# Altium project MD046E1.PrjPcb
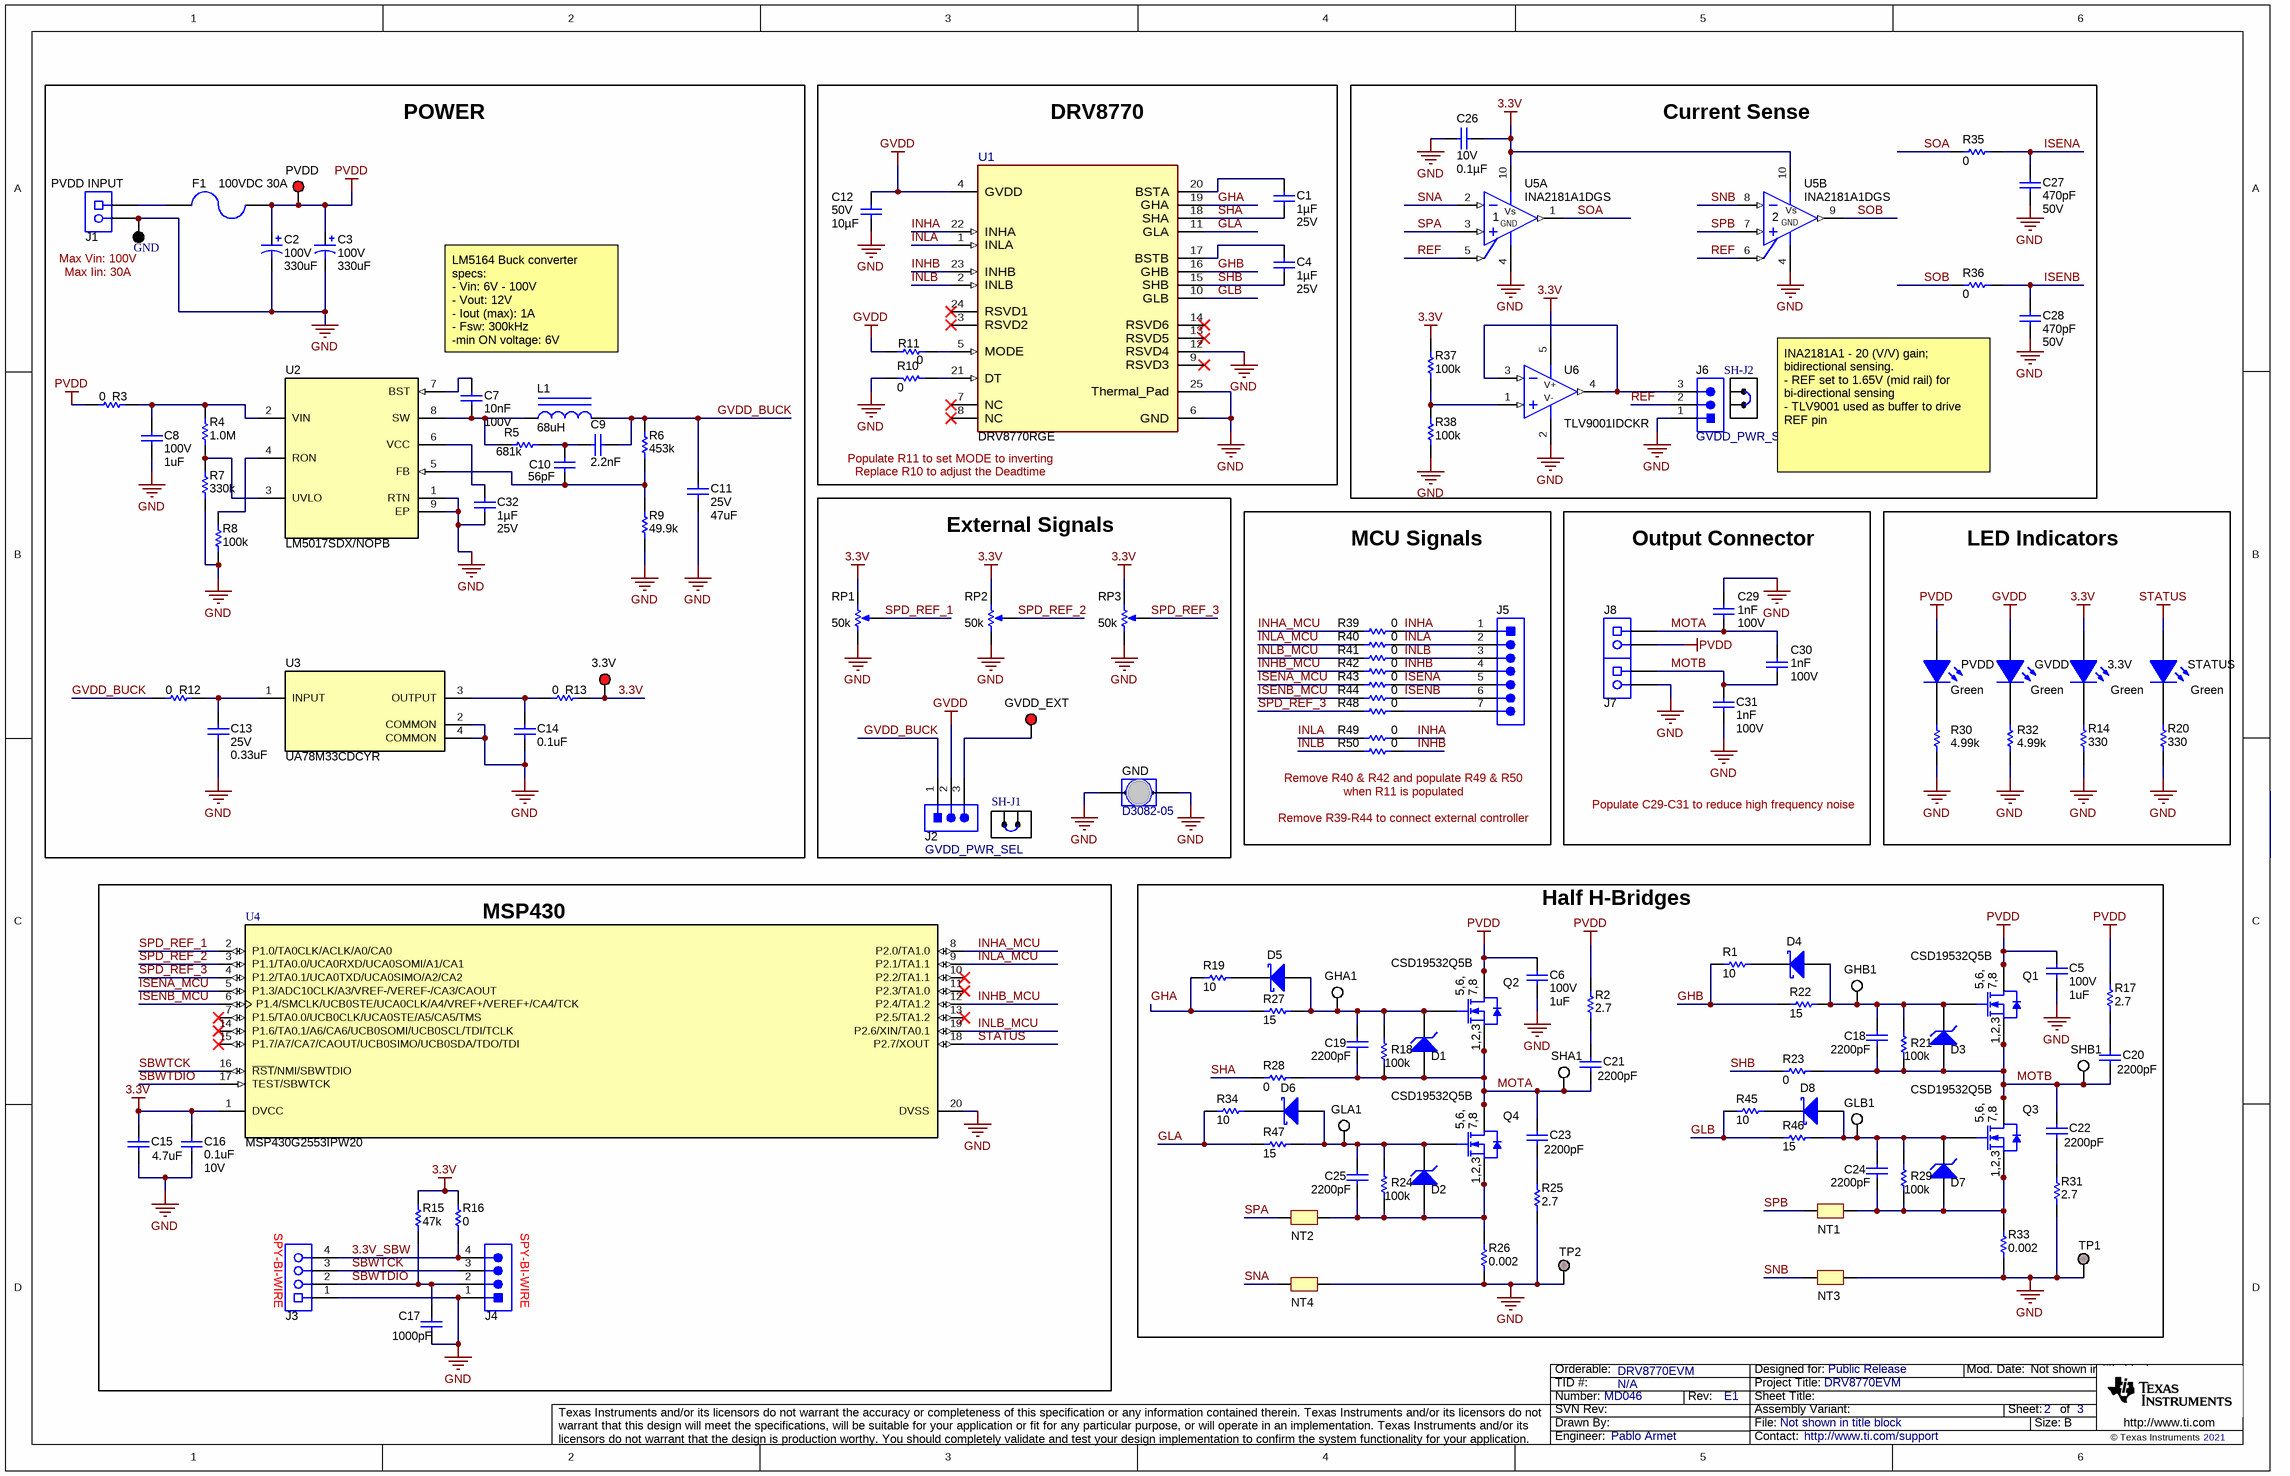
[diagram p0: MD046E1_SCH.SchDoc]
CopyrightYear: 2021; EVM_orderable: DRV8770EVM; PCB_Layout: Pablo Armet; PCB_Rev: E1; PRJ_Customer: Public Release; PRJ_Engineer: Pablo Armet; PRJ_Number: MD046; PRJ_Title: DRV8770EVM; SCH_Rev: E1; TechSupport: http://www.ti.com/support; TID: N/A
1 sheet, 136 parts. Net scope: global (net labels, ports and power ports of the same name join across sheets).
Board file: MD046E1_PCB.PcbDoc

## Sheet MD046E1_SCH.SchDoc
size 431 x 279 mm; Date: Not shown in title block; ApprovedBy: Not shown in title block; CheckedBy: Not shown in title block; Author: Not shown in title block; CompanyName: Not shown in title block; Engineer: Not shown in title block; Organization: Not shown in title block; Address1: Not shown in title block; Address2: Not shown in title block; Address3: Not shown in title block; Address4: Not shown in title block; DocumentNumber: 2; Revision: Use project parameter SCH_Rev; SheetNumber: 2; SheetTotal: 3; PageSetup: Record=PageOptions¦CenterHorizontal=True¦CenterVertical=True¦PrintScale=1.00¦XCorrection=1.00¦YCorrection=1.00¦PrintKind=0¦BorderSize=5000000¦LeftOffset=0¦BottomOffset=0¦Orientation=2¦PaperLength=1000¦PaperWidth=1000¦Scale=100¦PaperSource=15¦PrintQuality=600¦MediaType=1¦DitherType=10¦PaperKind=Letter¦PrintScaleMode=1

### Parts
(Parts that share a designator on the sheet are numbered #1, #2 ... from top to bottom, then left to right.)
3.3V#1  value Green  [LED_LTST-C171]
3.3V#2  (no value)  [Keystone5000]
C1  Cap_F: 1µF  VDC_V: 25V  [0805L]  (hidden comment: CL21B105KAFNNNE)
C2  VDC_V: 100V  ValueDisplayed: 330uF  [SM_RADIAL_K16]  (hidden comment: EEV-FK2A331M)
C3  VDC_V: 100V  ValueDisplayed: 330uF  [SM_RADIAL_K16]  (hidden comment: EEV-FK2A331M)
C4  Cap_F: 1µF  VDC_V: 25V  [0805L]  (hidden comment: CL21B105KAFNNNE)
C5  VDC_V: 100V  ValueDisplayed: 1uF  [1210_220L]  (hidden comment: CGA6M2X7R2A105K200AA)
C6  VDC_V: 100V  ValueDisplayed: 1uF  [1210_220L]  (hidden comment: CGA6M2X7R2A105K200AA)
C7  Cap_F: 10nF  VDC_V: 100V  [0603L]  (hidden comment: C0603C103J1RACTU)
C8  VDC_V: 100V  ValueDisplayed: 1uF  [1210_220]  (hidden comment: CGA6M2X7R2A105K200AA)
C9  Cap_F: 2.2nF  [0603L]  (hidden comment: CGA3E2X7R2A222K080AA)
C10  ValueDisplayed: 56pF  [0603L]  (hidden comment: GRM1885C2A560JA01D)
C11  VDC_V: 25V  ValueDisplayed: 47uF  [1206_190L]  (hidden comment: C3216X5R1E476M160AC)
C12  VDC_V: 50V  ValueDisplayed: 10µF  [1210_270L]  (hidden comment: CL32B106KBJNNWE)
C13  VDC_V: 25V  ValueDisplayed: 0.33uF  [0805L]  (hidden comment: 08053D334KAT2A)
C14  ValueDisplayed: 0.1uF  [0603L]  (hidden comment: C0603C104J4RACTU)
C15  ValueDisplayed: 4.7uF  [0402_065L]  (hidden comment: C1005X5R1A475K050BC)
C16  ValueDisplayed: 0.1uF  VDC_V: 10V  [0603L]  (hidden comment: C0603C104K8RACTU)
C17  ValueDisplayed: 1000pF  [0603L]  (hidden comment: C0603C102J5RACAUTO)
C18  ValueDisplayed: 2200pF  [0603L]  (hidden comment: 06031C222KAT2A)
C19  ValueDisplayed: 2200pF  [0603L]  (hidden comment: 06031C222KAT2A)
C20  ValueDisplayed: 2200pF  [0603L]  (hidden comment: GRM188R72A222KA01D)
C21  ValueDisplayed: 2200pF  [0603L]  (hidden comment: GRM188R72A222KA01D)
C22  ValueDisplayed: 2200pF  [0603L]  (hidden comment: GRM188R72A222KA01D)
C23  ValueDisplayed: 2200pF  [0603L]  (hidden comment: GRM188R72A222KA01D)
C24  ValueDisplayed: 2200pF  [0603L]  (hidden comment: 06031C222KAT2A)
C25  ValueDisplayed: 2200pF  [0603L]  (hidden comment: 06031C222KAT2A)
C26  VDC_V: 10V  ValueDisplayed: 0.1µF  [0402L]  (hidden comment: C0402C104K8RACAUTO)
C27  Cap_F: 470pF  VDC_V: 50V  [0603L]  (hidden comment: 885012206081)
C28  Cap_F: 470pF  VDC_V: 50V  [0603L]  (hidden comment: 885012206081)
C29  Cap_F: 1nF  VDC_V: 100V  [0603L]  (hidden comment: 06031C102JAT2A)
C30  Cap_F: 1nF  VDC_V: 100V  [0603L]  (hidden comment: 06031C102JAT2A)
C31  Cap_F: 1nF  VDC_V: 100V  [0603L]  (hidden comment: 06031C102JAT2A)
C32  Cap_F: 1µF  VDC_V: 25V  [0805L]  (hidden comment: CL21B105KAFNNNE)
D1  SMAZ16-13-F  [SMA]  (value not drawn)
D2  SMAZ16-13-F  [SMA]  (value not drawn)
D3  SMAZ16-13-F  [SMA]  (value not drawn)
D4  SSA24-E3/61T  [SMA]  (value not drawn)
D5  SSA24-E3/61T  [SMA]  (value not drawn)
D6  SSA24-E3/61T  [SMA]  (value not drawn)
D7  SMAZ16-13-F  [SMA]  (value not drawn)
D8  SSA24-E3/61T  [SMA]  (value not drawn)
F1  100VDC 30A  [Fuse_0463]
GHA1  5002  [Keystone5002]  (value not drawn)
GHB1  5002  [Keystone5002]  (value not drawn)
GLA1  5002  [Keystone5002]  (value not drawn)
GLB1  5002  [Keystone5002]  (value not drawn)
GND#1  5001  [Keystone5001]  (value not drawn)
GND#2  D3082-05  [Harwin_D3082-05]
GVDD  value Green  [LED_LTST-C171]
GVDD_EXT  (no value)  [Keystone5000]
J1  PVDD INPUT  [Phoenix_1902547]
J2  GVDD_PWR_SEL  [WURTH_61300311121]
J3  851-43-004-20-001000  [CONN_851-43-004-20-001000]  (value not drawn)
J4  TSW-104-07-G-S  [TSW-104-07-G-S]  (value not drawn)
J5  PBC07SFAN  [Sullins_xxC07SFAN]  (value not drawn)
J6  GVDD_PWR_SEL  [WURTH_61300311121]
J7  (no value)  [Phoenix_1902547]
J8  (no value)  [Phoenix_1902547]
L1  ValueDisplayed: 68uH  [SDR1006]  (hidden comment: SDR1006-680KL)
NT1  Net-Tie  [Net-Tie_10mil]  (value not drawn)  (net tie, no BOM)
NT2  Net-Tie  [Net-Tie_10mil]  (value not drawn)  (net tie, no BOM)
NT3  Net-Tie  [Net-Tie_10mil]  (value not drawn)  (net tie, no BOM)
NT4  Net-Tie  [Net-Tie_10mil]  (value not drawn)  (net tie, no BOM)
PVDD#1  5000  [Keystone5000]  (value not drawn)
PVDD#2  value Green  [LED_LTST-C171]
Q1  CSD19532Q5B  [DNK0008A]
Q2  CSD19532Q5B  [DNK0008A]
Q3  CSD19532Q5B  [DNK0008A]
Q4  CSD19532Q5B  [DNK0008A]
R1  ValueDisplayed: 10  [0805L]  (hidden comment: ERJ-6GEYJ100V)
R2  ValueDisplayed: 2.7  [0805L]  (hidden comment: CRCW08052R70JNEA)
R3  value 0  [0603L]  (hidden comment: CRCW06030000Z0EA)
R4  ValueDisplayed: 1.0M  [0603L]  (hidden comment: CRCW06031M00JNEA)
R5  ValueDisplayed: 681k  [0603L]  (hidden comment: RC0603FR-07681KL)
R6  ValueDisplayed: 453k  [0603L]  (hidden comment: RC0603FR-07453KL)
R7  ValueDisplayed: 330k  [0603L]  (hidden comment: CRCW0603330KJNEA)
R8  ValueDisplayed: 100k  [0402L]  (hidden comment: CRCW0402100KFKED)
R9  ValueDisplayed: 49.9k  [0603L]  (hidden comment: RC0603FR-0749K9L)
R10  ValueDisplayed: 0  [0805L]  (hidden comment: CRCW08050000Z0EAHP)
R11  value 0  [0603L]  (hidden comment: CRCW06030000Z0EA)
R12  value 0  [0603L]  (hidden comment: CRCW06030000Z0EA)
R13  value 0  [0603L]  (hidden comment: CRCW06030000Z0EA)
R14  ValueDisplayed: 330  [0603L]  (hidden comment: CRCW0603330RJNEA)
R15  ValueDisplayed: 47k  [0603L]  (hidden comment: CRCW060347K0JNEA)
R16  ValueDisplayed: 0  [0603L]  (hidden comment: CRCW06030000Z0EA)
R17  ValueDisplayed: 2.7  [0805L]  (hidden comment: CRCW08052R70JNEA)
R18  ValueDisplayed: 100k  [0603L]  (hidden comment: CRCW0603100KFKEA)
R19  ValueDisplayed: 10  [0805L]  (hidden comment: ERJ-6GEYJ100V)
R20  ValueDisplayed: 330  [0603L]  (hidden comment: CRCW0603330RJNEA)
R21  ValueDisplayed: 100k  [0603L]  (hidden comment: CRCW0603100KFKEA)
R22  ValueDisplayed: 15  [0805L]  (hidden comment: ERJ-6GEYJ150V)
R23  ValueDisplayed: 0  [0603L]  (hidden comment: RCS06030000Z0EA)
R24  ValueDisplayed: 100k  [0603L]  (hidden comment: CRCW0603100KFKEA)
R25  ValueDisplayed: 2.7  [0805L]  (hidden comment: CRCW08052R70JNEA)
R26  ValueDisplayed: 0.002  [LRMA2512_under3]  (hidden comment: LRMAP2512-R002FT4)
R27  ValueDisplayed: 15  [0805L]  (hidden comment: ERJ-6GEYJ150V)
R28  ValueDisplayed: 0  [0603L]  (hidden comment: RCS06030000Z0EA)
R29  ValueDisplayed: 100k  [0603L]  (hidden comment: CRCW0603100KFKEA)
R30  value 4.99k  [0603L]  (hidden comment: CRCW06034K99FKEA)
R31  ValueDisplayed: 2.7  [0805L]  (hidden comment: CRCW08052R70JNEA)
R32  value 4.99k  [0603L]  (hidden comment: CRCW06034K99FKEA)
R33  ValueDisplayed: 0.002  [LRMA2512_under3]  (hidden comment: LRMAP2512-R002FT4)
R34  ValueDisplayed: 10  [0805L]  (hidden comment: ERJ-6GEYJ100V)
R35  ValueDisplayed: 0  [0603L]  (hidden comment: RCS06030000Z0EA)
R36  ValueDisplayed: 0  [0603L]  (hidden comment: RCS06030000Z0EA)
R37  ValueDisplayed: 100k  [0603L]  (hidden comment: CRCW0603100KFKEA)
R38  ValueDisplayed: 100k  [0603L]  (hidden comment: CRCW0603100KFKEA)
R39  ValueDisplayed: 0  [0603L]  (hidden comment: RCS06030000Z0EA)
R40  ValueDisplayed: 0  [0603L]  (hidden comment: RCS06030000Z0EA)
R41  ValueDisplayed: 0  [0603L]  (hidden comment: RCS06030000Z0EA)
R42  ValueDisplayed: 0  [0603L]  (hidden comment: RCS06030000Z0EA)
R43  ValueDisplayed: 0  [0603L]  (hidden comment: RCS06030000Z0EA)
R44  ValueDisplayed: 0  [0603L]  (hidden comment: RCS06030000Z0EA)
R45  ValueDisplayed: 10  [0805L]  (hidden comment: ERJ-6GEYJ100V)
R46  ValueDisplayed: 15  [0805L]  (hidden comment: ERJ-6GEYJ150V)
R47  ValueDisplayed: 15  [0805L]  (hidden comment: ERJ-6GEYJ150V)
R48  ValueDisplayed: 0  [0603L]  (hidden comment: RCS06030000Z0EA)
R49  ValueDisplayed: 0  [0603L]  (hidden comment: RCS06030000Z0EA)
R50  ValueDisplayed: 0  [0603L]  (hidden comment: RCS06030000Z0EA)
RP1  value 50k  [Bourns_3352T]  (hidden comment: 3352T-1-503LF)
RP2  value 50k  [Bourns_3352T]  (hidden comment: 3352T-1-503LF)
RP3  value 50k  [Bourns_3352T]  (hidden comment: 3352T-1-503LF)
SH-J1  SNT-100-BK-G  [SNT-100-BK-G]  (value not drawn)
SH-J2  SNT-100-BK-G  [SNT-100-BK-G]  (value not drawn)
SHA1  5002  [Keystone5002]  (value not drawn)
SHB1  5002  [Keystone5002]  (value not drawn)
STATUS  value Green  [LED_LTST-C171]
TP1  TP_SM_1MM  [TP_SM_1MM]  (value not drawn)  (no BOM)
TP2  TP_SM_1MM  [TP_SM_1MM]  (value not drawn)  (no BOM)
U1  DRV8770RGE  [RGE0024B-MFG]
U2  LM5017SDX/NOPB  [NGU0008B]
U3  UA78M33CDCYR  [DCY0004A_N]
U4  MSP430G2553IPW20  [PW0020A_N]
U5  INA2181A1DGS  [DGS0010A_N]  (parts A,B of 2)
U6  TLV9001IDCKR  [DCK0005A_N]

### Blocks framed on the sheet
POWER: 3.3V#2 C2 C3 C7-C11 C13 C14 C32 F1 GND#1 J1 L1 PVDD#1 R3-R9 R12 R13 U2 U3
DRV8770: C1 C4 C12 R10 R11 U1
Current Sense: C26-C28 J6 R35-R38 SH-J2 U5 U6
External Signals: GND#2 GVDD_EXT J2 RP1-RP3 SH-J1
MCU Signals: J5 R39-R44 R48-R50
Output Connector: C29-C31 J7 J8
LED Indicators: 3.3V#1 GVDD PVDD#2 R14 R20 R30 R32 STATUS
MSP430: C15-C17 J3 J4 R15 R16 U4
Half H-Bridges: C5 C6 C18-C25 D1-D8 GHA1 GHB1 GLA1 GLB1 NT1-NT4 Q1-Q4 R1 R2 R17-R19 R21-R29 R31 R33 R34 R45-R47 SHA1 SHB1 TP1 TP2

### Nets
3.3V: 3.3V#1.1(A) 3.3V#2.1 C15.1 C16.1 C26.1 R13.2 R15.2 R16.2 R37.2 RP1.3(CW) RP2.3(CW) RP3.3(CW) U4.1(DVCC) U5.10(VS) U6.5(V+)
GND: C2.2(-) C3.2(-) C5.2 C6.2 C8.2 C11.2 C12.2 C13.2 C14.2 C15.2 C16.2 C17.2 C26.2 C27.2 C28.2 C29.1 C31.2 C32.2 GND#1.1 GND#2.1 GND#2.2 J1.2 J3.1 J4.1 J6.1 J7.2 NT3.2 NT4.2 R7.1 R8.1 R9.1 R10.1 R14.1 R20.1 R25.1 R26.1 R30.1 R31.1 R32.1 R33.1 R38.1 RP1.1(CCW) RP2.1(CCW) RP3.1(CCW) TP1.1 TP2.1 U1.6(GND) U1.12(RSVD4) U1.25(Thermal_Pad) U2.1(RTN) U2.9(EP) U3.2(COMMON) U3.4(COMMON) U4.20(DVSS) U5.4(GND) U6.2(V-)
GVDD: C12.1 GVDD.1(A) J2.2 R11.2 U1.4(GVDD)
PVDD: C2.1(+) C3.1(+) C5.1 C6.1 F1.1 J8.2 PVDD#1.1 PVDD#2.1(A) Q1.5(D) Q1.6(D) Q1.7(D) Q1.8(D) Q1.9(D) Q2.5(D) Q2.6(D) Q2.7(D) Q2.8(D) Q2.9(D) R2.2 R3.1 R17.2
STATUS: STATUS.1(A) U4.18(P2.7/XOUT)
3.3V_SBW: J3.4 J4.4 R16.1
GHA: R19.1 R27.1 U1.19(GHA)
GHB: R1.1 R22.1 U1.16(GHB)
GLA: R34.1 R47.1 U1.11(GLA)
GLB: R45.1 R46.1 U1.10(GLB)
GVDD_BUCK: C9.1 C11.1 J2.1 L1.2 R6.2 R12.1
INHA: J5.1 R39.2 R49.2 U1.22(INHA)
INHA_MCU: R39.1 U4.8(P2.0/TA1.0)
INHB: J5.4 R42.2 R50.2 U1.23(INHB)
INHB_MCU: R42.1 U4.12(P2.4/TA1.2)
INLA: J5.2 R40.2 R49.1 U1.1(INLA)
INLA_MCU: R40.1 U4.9(P2.1/TA1.1)
INLB: J5.3 R41.2 R50.1 U1.2(INLB)
INLB_MCU: R41.1 U4.19(P2.6/XIN/TA0.1)
ISENA: C27.1 J5.5 R35.2 R43.2
ISENA_MCU: R43.1 U4.5(P1.3/ADC10CLK/A3/VREF-/VEREF-/CA3/CAOUT)
ISENB: C28.1 J5.6 R36.2 R44.2
ISENB_MCU: R44.1 U4.6(P1.4/SMCLK/UCB0STE/UCA0CLK/A4/VREF+/VEREF+/CA4/TCK)
MOTA: C19.2 C21.2 C23.1 C29.2 C30.1 D1.2(A) J8.1 Q2.1(S) Q2.2(S) Q2.3(S) Q4.5(D) Q4.6(D) Q4.7(D) Q4.8(D) Q4.9(D) R18.2 R28.2 SHA1.1
MOTB: C18.2 C20.2 C22.1 C30.2 C31.1 D3.2(A) J7.1 Q1.1(S) Q1.2(S) Q1.3(S) Q3.5(D) Q3.6(D) Q3.7(D) Q3.8(D) Q3.9(D) R21.2 R23.2 SHB1.1
REF: J6.2 U5.5(REF1) U5.6(REF2)
SBWTCK: J3.3 J4.3 U4.16(~{RST}/NMI/SBWTDIO)
SBWTDIO: C17.1 J3.2 J4.2 R15.1 U4.17(TEST/SBWTCK)
SHA: C1.2 R28.1 U1.18(SHA)
SHB: C4.2 R23.1 U1.15(SHB)
SNA: NT4.1 U5.2(IN-1)
SNB: NT3.1 U5.8(IN-2)
SOA: R35.1 U5.1(OUT1)
SOB: R36.1 U5.9(OUT2)
SPA: NT2.1 U5.3(IN+1)
SPB: NT1.1 U5.7(IN+2)
SPD_REF_1: RP1.2(WIPER) U4.2(P1.0/TA0CLK/ACLK/A0/CA0)
SPD_REF_2: RP2.2(WIPER) U4.3(P1.1/TA0.0/UCA0RXD/UCA0SOMI/A1/CA1)
SPD_REF_3: R48.1 RP3.2(WIPER) U4.4(P1.2/TA0.1/UCA0TXD/UCA0SIMO/A2/CA2)
Net3.3V#1_2: 3.3V#1.2(K) R14.2
NetC1_1: C1.1 U1.20(BSTA)
NetC4_1: C4.1 U1.17(BSTB)
NetC7_1: C7.1 U2.7(BST)
NetC7_2: C7.2 L1.1 R5.1 U2.8(SW)
NetC8_1: C8.1 R3.2 R4.2 U2.2(VIN)
NetC9_2: C9.2 C10.1 R5.2
NetC10_2: C10.2 R6.1 R9.2 U2.5(FB)
NetC13_1: C13.1 R12.2 U3.1(INPUT)
NetC14_1: C14.1 R13.1 U3.3(OUTPUT)
NetC18_1: C18.1 D3.1(K) D4.2(A) GHB1.1 Q1.4(G) R21.1 R22.2
NetC19_1: C19.1 D1.1(K) D5.2(A) GHA1.1 Q2.4(G) R18.1 R27.2
NetC20_1: C20.1 R17.1
NetC21_1: C21.1 R2.1
NetC22_2: C22.2 R31.2
NetC23_2: C23.2 R25.2
NetC24_1: C24.1 D7.1(K) D8.2(A) GLB1.1 Q3.4(G) R29.1 R46.2
NetC24_2: C24.2 D7.2(A) NT1.2 Q3.1(S) Q3.2(S) Q3.3(S) R29.2 R33.2
NetC25_1: C25.1 D2.1(K) D6.2(A) GLA1.1 Q4.4(G) R24.1 R47.2
NetC25_2: C25.2 D2.2(A) NT2.2 Q4.1(S) Q4.2(S) Q4.3(S) R24.2 R26.2
NetC32_1: C32.1 U2.6(VCC)
NetD4_1: D4.1(K) R1.2
NetD5_1: D5.1(K) R19.2
NetD6_1: D6.1(K) R34.2
NetD8_1: D8.1(K) R45.2
NetF1_2: F1.2 J1.1
NetGVDD_2: GVDD.2(K) R32.2
NetGVDD_EXT_1: GVDD_EXT.1 J2.3
NetJ5_7: J5.7 R48.2
NetJ6_3: J6.3 U6.3(IN-) U6.4(OUT)
NetPVDD#2_2: PVDD#2.2(K) R30.2
NetR4_1: R4.1 R7.2 U2.3(UVLO)
NetR8_2: R8.2 U2.4(RON)
NetR10_2: R10.2 U1.21(DT)
NetR11_1: R11.1 U1.5(MODE)
NetR20_2: R20.2 STATUS.2(K)
NetR37_1: R37.1 R38.2 U6.1(IN+)

Not connected (* = marked no-connect by the designer): U1 3(RSVD2)* 7(NC)* 8(NC)* 9(RSVD3)* 13(RSVD5)* 14(RSVD6)* 24(RSVD1)*; U4 7(P1.5/TA0.0/UCB0CLK/UCA0STE/A5/CA5/TMS)* 10(P2.2/TA1.1)* 11(P2.3/TA1.0)* 13(P2.5/TA1.2)* 14(P1.6/TA0.1/A6/CA6/UCB0SOMI/UCB0SCL/TDI/TCLK)* 15(P1.7/A7/CA7/CAOUT/UCB0SIMO/UCB0SDA/TDO/TDI)*

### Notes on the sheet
- Max Vin: 100V
- Max Iin: 30A
- LM5164 Buck converter specs:
  - Vin: 6V - 100V
  - Vout: 12V
  - Iout (max): 1A
  - Fsw: 300kHz
  -min ON voltage: 6V
- (near U1) Replace R10 to adjust the Deadtime
- (near U1) Populate R11 to set MODE to inverting
- INA2181A1 - 20 (V/V) gain; bidirectional sensing.
  - REF set to 1.65V (mid rail) for bi-directional sensing
  - TLV9001 used as buffer to drive REF pin
- Remove R39-R44 to connect external controller
- Remove R40 & R42 and populate R49 & R50
- when R11 is populated
- Populate C29-C31 to reduce high frequency noise
- (near J3) SPY-BI-WIRE
- (near J4) SPY-BI-WIRE

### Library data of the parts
3.3V#1 GVDD PVDD#2 STATUS = CMP-0002830-3: LED, Green, SMD; Manufacturer: Lite-On; PartNumber: LTST-C171GKT; Vf_V: 2.1V; Io_A: 20A; Value1: W; SizeArea_mm2: 2.5; SizeAreaWB_mm2: 6.75; SizeX_mm: 2; SizeY_mm: 1.25; SizeZ_mm: 1.2
3.3V#2 GVDD_EXT = CMP-0055137-1: Test Point, Miniature, Red, TH; PartNumber: 5000; Manufacturer: Keystone; ContactFinish: Silver; CNHeader: FALSE; CT: TRUE; Green_Lifecycle: Active; Green_REACh: Passed
C1 C4 C32 = CMP-0083859-1: CAP, CERM, 1 µF, 25 V,+/- 10%, X7R, 0805; Manufacturer: Samsung Electro-Mechanics; TaMin_C: -55°C; Polarized: N; Green_Lifecycle: Active; SizeAreaWB_mm2: 6.75; Green_REACh: Passed; U/M: EA; Value: 1uF; TaMax_C: 125°C; SizeZ_mm: 1.45; SizeX_mm: 2; SizeY_mm: 1.25; Cap_Case: 0805; SizeArea_mm2: 2.5; AEC Category: Q200
C2 C3 = CMP-0011224-2: CAP, AL, 330 uF, 100 V, +/- 20%, 0.153 ohm, AEC-Q200 Grade 2, SMD; Manufacturer: Panasonic; TaMin_C: -55°C; ESR_ohm: 1.53d; Polarized: Y; SizeAreaWB_mm2: 483; U/M: EA; Value: 330uF; TaMax_C: 105°C; SizeZ_mm: 16.5; SizeX_mm: 21; SizeY_mm: 19; Cap_Case: K16; SizeArea_mm2: 399; CompType: Capacitor; Cap_F: 330µF; IRMS_A: 9.17dA; AEC Grade: 2; AEC Category: Q200
C5 C6 = CMP-0009145-2: CAP, CERM, 1 uF, 100 V, +/- 10%, X7R, AEC-Q200 Grade 1, 1210; Manufacturer: TDK; TaMin_C: -55°C; ESR_ohm: 4.956m; Polarized: N; SizeAreaWB_mm2: 14.7; Value1: 0.004956 ohm; U/M: EA; Value: 1uF; TaMax_C: 125°C; SizeZ_mm: 2.2; SizeX_mm: 3.2; SizeY_mm: 2.5; Cap_Case: 1210_220; SizeArea_mm2: 8; AEC Qualified: Y; Cap_F: 1µF; IRMS_A: 3.30731A; AEC Grade: 1; AEC Category: Q200
C7 = CMP-0006848-4: CAP, CERM, 0.01 uF, 100 V, +/- 5%, X7R, 0603; Manufacturer: Kemet; TaMin_C: -55°C; Polarized: N; SizeAreaWB_mm2: 4.68; Value1: Unknown; U/M: EA; Value: 0.01uF; TaMax_C: 125°C; SizeZ_mm: 1; SizeX_mm: 1.6; SizeY_mm: 0.8; Cap_Case: 0603; SizeArea_mm2: 1.28; AEC Category: Q200
C8 = CMP-0009145-2: CAP, CERM, 1 uF, 100 V, +/- 10%, X7R, AEC-Q200 Grade 1, 1210; Manufacturer: TDK; TaMin_C: -55°C; ESR_ohm: 4.956m; Polarized: N; SizeAreaWB_mm2: 14.7; Value1: 0.004956 ohm; U/M: EA; Value: 1uF; TaMax_C: 125°C; SizeZ_mm: 2.2; SizeX_mm: 3.2; SizeY_mm: 2.5; SizeArea_mm2: 8; AEC Qualified: Y; Cap_F: 1µF; IRMS_A: 3.30731A; AEC Grade: 1; AEC Category: Q200
C9 = CMP-0007085-4: CAP, CERM, 2200 pF, 100 V, +/- 10%, X7R, AEC-Q200 Grade 1, 0603; Manufacturer: TDK; TaMin_C: -55°C; ESR_ohm: 0.923948; Polarized: N; SizeAreaWB_mm2: 4.68; Value1: 0.923948 ohm; U/M: EA; Value: 2200pF; TaMax_C: 125°C; SizeZ_mm: 1; SizeX_mm: 1.6; SizeY_mm: 0.8; Cap_Case: 0603; Value2: 100V; SizeArea_mm2: 1.28; AEC Qualified: Y; IRMS_A: 295.638mA; AEC Category: Q200
C10 = CMP-0007275-4: CAP, CERM, 56 pF, 100 V, +/- 5%, C0G/NP0, 0603; Manufacturer: MuRata; TaMin_C: -55°C; Polarized: N; SizeAreaWB_mm2: 4.68; Value1: Unknown; U/M: EA; Value: 56pF; TaMax_C: 125°C; SizeZ_mm: 1; SizeX_mm: 1.6; SizeY_mm: 0.8; Cap_Case: 0603; Value2: 100V; SizeArea_mm2: 1.28; AEC Category: Q200
C11 = CMP-0008656-2: CAP, CERM, 47 uF, 25 V, +/- 20%, X5R, 1206_190; Manufacturer: TDK; TaMin_C: -55°C; Polarized: N; SizeAreaWB_mm2: 10.92; Value1: Unknown; U/M: EA; Value: 47uF; TaMax_C: 85°C; SizeZ_mm: 1.9; SizeX_mm: 3.2; SizeY_mm: 1.6; Cap_Case: 1206; SizeArea_mm2: 5.12; Cap_F: 47µF; AEC Category: Q200
C12 = CMP-0079201-1: CAP, CERM, 10 µF, 50 V,+/- 10%, X7R, 1210; Manufacturer: Samsung Electro-Mechanics; TaMin_C: -55°C; ESR_ohm: 5m; Polarized: N; SizeAreaWB_mm2: 14.7; Value1: 0.005 ohm; U/M: EA; Value: 10uF; TaMax_C: 125°C; SizeZ_mm: 2.7; SizeX_mm: 3.2; SizeY_mm: 2.5; Cap_Case: 1210; SizeArea_mm2: 8; AEC Category: Q200
C13 = CMP-0007575-2: CAP, CERM, 0.33 uF, 25 V, +/- 10%, X5R, 0805; Manufacturer: AVX; TaMin_C: -55°C; ESR_ohm: 0.02; Polarized: N; SizeAreaWB_mm2: 6.75; Value1: 0.02 ohm; U/M: EA; Value: 0.33uF; TaMax_C: 85°C; SizeZ_mm: 1.45; SizeX_mm: 2; SizeY_mm: 1.25; Cap_Case: 0805; SizeArea_mm2: 2.5; Cap_F: 330nF; AEC Category: Q200
C14 = CMP-0006857-4: CAP, CERM, 0.1 uF, 16 V, +/- 5%, X7R, 0603; Manufacturer: Kemet; Polarized: N; CompType: Capacitor; Value: 0.1uF; U/M: EA; Cap_F: 100nF; Value1: Unknown; VDC_V: 16V; TaMin_C: -55°C; TaMax_C: 125°C; Cap_Case: 0603; AEC Category: Q200; SizeArea_mm2: 1.28; SizeAreaWB_mm2: 4.68; SizeX_mm: 1.6; SizeY_mm: 0.8; SizeZ_mm: 1
C15 = CMP-0006268-2: CAP, CERM, 4.7 uF, 10 V, +/- 10%, X5R, 0402; Manufacturer: TDK; TaMin_C: -55°C; ESR_ohm: 3.417m; Polarized: N; SizeAreaWB_mm2: 3; Value1: 0.003417 ohm; U/M: EA; Value: 4.7uF; TaMax_C: 85°C; SizeZ_mm: 0.65; SizeX_mm: 1; SizeY_mm: 0.5; Cap_Case: 0402_065; Value2: 10V; Cap_F: 4.7µF; IRMS_A: 2.7063A; AEC Category: Q200
C16 = CMP-0006862-5: CAP, CERM, 0.1 uF, 10 V, +/- 10%, X7R, 0603; Manufacturer: Kemet; Polarized: N; Value: 0.1uF; U/M: EA; Cap_F: 100nF; Value1: Unknown; TaMin_C: -55°C; TaMax_C: 125°C; Cap_Case: 0603; AEC Category: Q200; SizeAreaWB_mm2: 4.68; SizeZ_mm: 1; SizeX_mm: 1.6; SizeY_mm: 0.8; SizeArea_mm2: 1.28
C17 = CMP-0006844-4: CAP, CERM, 1000 pF, 50 V, +/- 5%, X7R, AEC-Q200 Grade 1, 0603; Manufacturer: Kemet; Polarized: N; Value: 1000pF; U/M: EA; Cap_F: 1nF; Value1: Unknown; VDC_V: 50V; TaMin_C: -55°C; TaMax_C: 125°C; Cap_Case: 0603; AEC Category: Q200; AEC Qualified: Y; AEC Grade: 1; SizeAreaWB_mm2: 4.68; SizeX_mm: 1.6; SizeY_mm: 0.8; SizeArea_mm2: 1.28
C18 C19 C24 C25 = CMP-0006737-4: CAP, CERM, 2200 pF, 100 V, +/- 10%, X7R, 0603; Manufacturer: AVX; TaMin_C: -55°C; ESR_ohm: 1.92d; Polarized: N; SizeAreaWB_mm2: 4.68; Value1: 0.192 ohm; U/M: EA; Value: 2200pF; TaMax_C: 125°C; SizeZ_mm: 1; SizeX_mm: 1.6; SizeY_mm: 0.8; Cap_Case: 0603; Value2: 100V; SizeArea_mm2: 1.28; CompType: Capacitor; Cap_F: 2.2nF; AEC Category: Q200
C20-C23 = CMP-0007475-4: CAP, CERM, 2200 pF, 100 V, +/- 10%, X7R, 0603; Manufacturer: MuRata; TaMin_C: -55°C; Polarized: N; SizeAreaWB_mm2: 4.68; Value1: Unknown; U/M: EA; Value: 2200pF; TaMax_C: 125°C; SizeZ_mm: 1; SizeX_mm: 1.6; SizeY_mm: 0.8; Cap_Case: 0603; Value2: 100V; SizeArea_mm2: 1.28; CompType: Capacitor; Cap_F: 2.2nF; AEC Category: Q200
C26 = CMP-0079150-1: CAP, CERM, 0.1 µF, 10 V,+/- 10%, X7R, AEC-Q200 Grade 1, 0402; Manufacturer: Kemet; Cap_F: 100nF; SizeAreaWB_mm2: 3; SizeArea_mm2: 0.5; AEC Qualified: Y; AEC Category: Q200; Value: 0.1uF; TaMax_C: 125°C; SizeZ_mm: 0.6; AEC Grade: 1; Polarized: N; TaMin_C: -55°C; U/M: EA; Cap_Case: 0402
C27 C28 = CMP-0006834-5: CAP, CERM, 470 pF, 50 V, +/- 10%, X7R, 0603; Manufacturer: Wurth Elektronik; TaMin_C: -55°C; Polarized: N; SizeAreaWB_mm2: 4.68; Value1: Unknown; U/M: EA; Value: 470pF; TaMax_C: 125°C; SizeZ_mm: 1; SizeX_mm: 1.6; SizeY_mm: 0.8; Cap_Case: 0603; SizeArea_mm2: 1.28; AEC Category: Q200
C29-C31 = CMP-0006723-4: CAP, CERM, 1000 pF, 100 V, +/- 5%, X7R, 0603; Manufacturer: AVX; TaMin_C: -55°C; ESR_ohm: 0.276; Polarized: N; SizeAreaWB_mm2: 4.68; Value1: 0.276 ohm; U/M: EA; Value: 1000pF; TaMax_C: 125°C; SizeZ_mm: 1; SizeX_mm: 1.6; SizeY_mm: 0.8; Cap_Case: 0603; SizeArea_mm2: 1.28; AEC Category: Q200
D1-D3 D7 = CMP-0005527-4: Diode, Zener, 16 V, 1 W, SMA; Manufacturer: Diodes Inc.; Value: 16V; RJA_CperW: 100; SizeY_mm: 2.92; AEC Category: Q101; SizeAreaWB_mm2: 37.3428; SizeX_mm: 5.59; AEC Qualified: N; SizeArea_mm2: 16.3228; SizeZ_mm: 2.87; Value1: 1W
D4-D6 D8 = CMP-0076923-3: Diode, Schottky, 40 V, 2 A, SMA; Manufacturer: Vishay-Semiconductor; Io_A: 2A; SizeAreaWB_mm2: 37.3428; Value: 40V; SizeY_mm: 2.92; AEC Qualified: N; SizeX_mm: 5.59; Green_Lifecycle: Not Set; SizeArea_mm2: 16.3228; Value2: 0.49V; RJC_CperW: 28.0; AEC Category: Q101; Green_REACh: Incomplete; Vf_V: 490mV; TJmax_C: 150°C; SizeZ_mm: 2.87
F1 = CMP-0077200-3: Fuse, 30 A, 250 VAC, 100 VDC, SMD; PartNumber: 0463030.ER; Manufacturer: Littelfuse; VAC_V: 250V; SizeAreaWB_mm2: 61.952; Rtyp_Ohm: 1.93m; SizeArea_mm2: 31.512; MeltingTyp: 916; SizeZ_mm: 3.12; VDC_V: 100V; SizeX_mm: 10.1; Interrupt_AC: 100A; Interrupt_DC: 50A; Fuse Speed: Fast; Fuse Technology: Board Mount; TaMax_C: 125°C; TaMin_C: -55°C
GHA1 GHB1 GLA1 GLB1 SHA1 SHB1 = CMP-0055139-1: Test Point, Miniature, White, TH; Manufacturer: Keystone; ContactFinish: Silver; CNHeader: FALSE; CT: TRUE; Green_Lifecycle: Active; Green_REACh: Passed
GND#1 = CMP-0055138-1: Test Point, Miniature, Black, TH; Manufacturer: Keystone; CNHeader: FALSE; Green_Lifecycle: Active; Green_REACh: Passed; ContactFinish: Silver; CT: TRUE
GND#2 = CMP-0075110-1: 1mm Uninsulated Shorting Plug, 10.16mm spacing, TH; Manufacturer: Harwin; CNHeader: False; Green_Lifecycle: Active; Green_REACh: Passed; CompType: Jumper Wire
J1 J7 J8 = CMP-0055527-1: Terminal Block, 9.52mm, 2x1, R/A, TH; PartNumber: 1902547; Manufacturer: Phoenix Contact; Pitch_mm: 9.52; Gender: Female; Row_Count: 1; Current_A: 32A; Voltage_V: 1kV; Cert_UL: Y; CNHeader: FALSE; CT: TRUE
J2 J6 = CMP-0054796-2: Header, 2.54 mm, 3x1, Gold, TH; Manufacturer: Wurth Elektronik; PartNumber: 61300311121; Green_Lifecycle: Active; Green_REACh: Passed; Cert_UL: Y; Gender: Male; Pitch_mm: 2.54; Row_Count: 1; Shrouded: N
J3 = CMP-0055060-1: SOCKET .050" GRID SIP 4 POS R/A, TH; Manufacturer: Mill-Max; CompType: Socket Strip; CNHeader: FALSE; CT: TRUE; Gender: Female; Green_Lifecycle: Active; Green_REACh: Passed
J4 = CMP-0075409-2: Header, 100mil, 4x1, Gold, TH; Manufacturer: Samtec; Pitch_mm: 2.54; Cert_VDE: N; Gender: Male; Cert_CSA: Y; Voltage_V: 550V; Green_REACh: Passed; Current_A: 6.3A; Green_Lifecycle: Active; Row_Count: 1
J5 = CMP-0054600-1: Header, 2.54 mm, Gold, 7x1, TH; Manufacturer: Sullins Connector Solutions; CNHeader: TRUE; Current_A: 3A; Gender: Male; Voltage_V: 1.8kV; Row_Count: 1; Pitch_mm: 2.54; CT: FALSE; Cert_UL: Y
L1 = CMP-0057541-2: Inductor, Drum Core, Ferrite, 68 uH, 1.1 A, 0.22 ohm, SMD; Manufacturer: Bourns; Isat: 2A @ 10% inductance drop; Irms: 1.1A @ 40C rise; Green_Lifecycle: Active; SizeAreaWB_mm2: 139.24; DCR_ohm: 0.22; Green_REACh: Passed; Value: 68uH; Imax_A: 1.1A; SizeZ_mm: 5.8; SizeX_mm: 9.8; SizeArea_mm2: 96.04; Ind_H: 68µH; AEC Category: Q200
NT1-NT4 = CMP-0078142-4: Single point connection between nets.
PVDD#1 = CMP-0055137-1: Test Point, Miniature, Red, TH; Manufacturer: Keystone; ContactFinish: Silver; CNHeader: FALSE; CT: TRUE; Green_Lifecycle: Active; Green_REACh: Passed
Q1-Q4 = CMP-0000958-3: MOSFET, N-CH, 100 V, 17 A, DNK0008A (VSON-CLIP-8); Manufacturer: Texas Instruments; Alternate Manufacturer: None; U/M: EA; ChType: N; Value: 100V; Value2: 48 nC; QgTyp_nC: 48; Vgs_V: 20V; IdsMax_A: 17A; SizeAreaWB_mm2: 56; SizeArea_mm2: 30; SizeX_mm: 6; SizeY_mm: 5; SizeZ_mm: 1; AEC Category: Q101
R1 R19 R34 R45 = CMP-0020617-3: RES, 10, 5%, 0.125 W, AEC-Q200 Grade 0, 0805; Manufacturer: Panasonic; Power_W: 125mW; TempCo: 200 ppm/C; Value_Code: 10R0; Value: 10; EIA_Code: E24; SizeX_mm: 2; SizeY_mm: 1.25; SizeZ_mm: 1.45; Value2: 0.125W; SizeArea_mm2: 2.5; AEC Qualified: Y; VDC_V: 150V; AEC Category: Q200; AEC Grade: 0; SizeAreaWB_mm2: 6.75
R2 R17 R25 R31 = CMP-0020521-3: RES, 2.7, 5%, 0.125 W, AEC-Q200 Grade 0, 0805; Manufacturer: Vishay-Dale; Power_W: 125mW; TempCo: 200 ppm/C; Value_Code: 2R70; Value: 2.7; EIA_Code: E24; SizeX_mm: 2; SizeY_mm: 1.25; SizeZ_mm: 1.45; Value2: 0.125W; SizeArea_mm2: 2.5; AEC Qualified: Y; VDC_V: 150V; AEC Category: Q200; AEC Grade: 0
R3 R11-R13 = CMP-0025697-4: RES, 0, 5%, 0.1 W, AEC-Q200 Grade 0, 0603; Manufacturer: Vishay-Dale; Value_Code: 0000; Power_W: 100mW; Value2: 0.1W; VDC_V: 75V; TempCo: 200 ppm/C; EIA_Code: E24; AEC Category: Q200; AEC Qualified: Y; SizeArea_mm2: 1.28; SizeX_mm: 1.6; SizeY_mm: 0.8; SizeZ_mm: 1
R4 = CMP-0025736-4: RES, 1.0 M, 5%, 0.1 W, AEC-Q200 Grade 0, 0603; Manufacturer: Vishay-Dale; Power_W: 100mW; TempCo: 200 ppm/C; Value_Code: 1M00; Value: 1.0Meg; EIA_Code: E24; Res_ohm: 1M; SizeX_mm: 1.6; SizeY_mm: 0.8; SizeZ_mm: 1; Value2: 0.1W; SizeArea_mm2: 1.28; AEC Qualified: Y; VDC_V: 75V; AEC Category: Q200; AEC Grade: 0
R5 = CMP-0023236-4: RES, 681 k, 1%, 0.1 W, 0603; Manufacturer: Yageo; Power_W: 100mW; TempCo: 100 ppm/C; Value: 681k; EIA_Code: E96; SizeX_mm: 1.6; SizeY_mm: 0.8; SizeZ_mm: 1; Value2: 0.1W; SizeArea_mm2: 1.28; AEC Qualified: N; VDC_V: 75V; AEC Category: Q200; SizeAreaWB_mm2: 4.68
R6 = CMP-0023120-4: RES, 453 k, 1%, 0.1 W, 0603; Manufacturer: Yageo; Power_W: 100mW; TempCo: 100 ppm/C; Value: 453k; EIA_Code: E96; SizeX_mm: 1.6; SizeY_mm: 0.8; SizeZ_mm: 1; Value2: 0.1W; SizeArea_mm2: 1.28; AEC Qualified: N; VDC_V: 75V; AEC Category: Q200; SizeAreaWB_mm2: 4.68
R7 = CMP-0025784-4: RES, 330 k, 5%, 0.1 W, AEC-Q200 Grade 0, 0603; Manufacturer: Vishay-Dale; Power_W: 100mW; TempCo: 200 ppm/C; Value: 330k; EIA_Code: E24; SizeX_mm: 1.6; SizeY_mm: 0.8; SizeZ_mm: 1; Value2: 0.1W; SizeArea_mm2: 1.28; AEC Qualified: Y; VDC_V: 75V; AEC Category: Q200; AEC Grade: 0
R8 = CMP-0025950-3: RES, 100 k, 1%, 0.063 W, AEC-Q200 Grade 0, 0402; Manufacturer: Vishay-Dale; Power_W: 63mW; TempCo: 100 ppm/C; Value: 100k; EIA_Code: E96; SizeX_mm: 1; SizeY_mm: 0.5; SizeZ_mm: 0.6; Value2: 0.063W; AEC Qualified: Y; VDC_V: 50V; AEC Category: Q200; AEC Grade: 0
R9 = CMP-0023142-5: RES, 49.9 k, 1%, 0.1 W, 0603; Manufacturer: Yageo; Power_W: 100mW; TempCo: 100 ppm/C; Value_Code: 49k9; Value: 49.9k; EIA_Code: E96; SizeX_mm: 1.6; SizeY_mm: 0.8; SizeZ_mm: 1; Value2: 0.1W; SizeArea_mm2: 1.28; AEC Qualified: N; VDC_V: 75V; AEC Category: Q200; SizeAreaWB_mm2: 4.68
R10 = CMP-0020443-3: RES, 0, 5%, 0.333 W, AEC-Q200 Grade 0, 0805; Manufacturer: Vishay-Dale; Power_W: 333mW; TempCo: 200 ppm/C; Value_Code: 0000; Value: 0; EIA_Code: E24; SizeX_mm: 2; SizeY_mm: 1.25; SizeZ_mm: 1.45; Value2: 0.333W; SizeArea_mm2: 2.5; AEC Qualified: Y; AEC Category: Q200; VDC_V: 150V
R14 R20 = CMP-0025785-4: RES, 330, 5%, 0.1 W, AEC-Q200 Grade 0, 0603; Manufacturer: Vishay-Dale; Power_W: 100mW; TempCo: 200 ppm/C; Value_Code: 330R; Value: 330; EIA_Code: E24; SizeX_mm: 1.6; SizeY_mm: 0.8; SizeZ_mm: 1; Value2: 0.1W; SizeArea_mm2: 1.28; CompType: Resistor; AEC Qualified: Y; VDC_V: 75V; AEC Category: Q200; AEC Grade: 0
R15 = CMP-0025814-4: RES, 47 k, 5%, 0.1 W, AEC-Q200 Grade 0, 0603; Manufacturer: Vishay-Dale; Value: 47k; Value_Code: 47k0; Power_W: 100mW; Value2: 0.1W; VDC_V: 75V; TempCo: 200 ppm/C; EIA_Code: E24; AEC Category: Q200; AEC Qualified: Y; AEC Grade: 0; SizeX_mm: 1.6; SizeY_mm: 0.8; SizeZ_mm: 1; SizeArea_mm2: 1.28
R16 = CMP-0025697-4: RES, 0, 5%, 0.1 W, AEC-Q200 Grade 0, 0603; Manufacturer: Vishay-Dale; Value: 0; Value_Code: 0000; Power_W: 100mW; Value2: 0.1W; VDC_V: 75V; TempCo: 200 ppm/C; EIA_Code: E24; AEC Category: Q200; AEC Qualified: Y; SizeX_mm: 1.6; SizeY_mm: 0.8; SizeZ_mm: 1; SizeArea_mm2: 1.28
R18 R21 R24 R29 R37 R38 = CMP-0021990-4: RES, 100 k, 1%, 0.1 W, AEC-Q200 Grade 0, 0603; Manufacturer: Vishay-Dale; Power_W: 100mW; TempCo: 100 ppm/C; Value: 100k; EIA_Code: E96; SizeX_mm: 1.6; SizeY_mm: 0.8; SizeZ_mm: 1; Value2: 0.1W; SizeArea_mm2: 1.28; AEC Qualified: Y; VDC_V: 75V; AEC Category: Q200; AEC Grade: 0
R22 R27 R46 R47 = CMP-0020643-3: RES, 15, 5%, 0.125 W, AEC-Q200 Grade 0, 0805; Manufacturer: Panasonic; Power_W: 125mW; TempCo: 200 ppm/C; Value_Code: 15R0; Value: 15; EIA_Code: E24; SizeX_mm: 2; SizeY_mm: 1.25; SizeZ_mm: 1.45; Value2: 0.125W; SizeArea_mm2: 2.5; AEC Qualified: Y; VDC_V: 150V; AEC Category: Q200; AEC Grade: 0; SizeAreaWB_mm2: 6.75
R23 R28 R35 R36 R39-R44 R48-R50 = CMP-0081973-1: RES, 0, 0%, 0.25 W, AEC-Q200 Grade 0, 0603; Manufacturer: Vishay-Dale; SizeAreaWB_mm2: 4.68; SizeArea_mm2: 1.28; AEC Qualified: Y; AEC Category: Q200; Value: 0; SizeZ_mm: 1; SizeY_mm: 0.8; Power_W: 250mW; Value2: 0.25W; SizeX_mm: 1.6
R26 R33 = CMP-0015826-2: RES, 0.002, 1%, 3 W, AEC-Q200 Grade 0, 2512; Manufacturer: TT Electronics/IRC; Power_W: 3W; TempCo: 50 ppm/C; Value_Code: 2L000; U/M: EA; Value: 0.002; Res_ohm: 2m; AEC Qualified: Y; AEC Grade: 0; AEC Category: Q200
R30 R32 = CMP-0022458-4: RES, 4.99 k, 1%, 0.1 W, AEC-Q200 Grade 0, 0603; Manufacturer: Vishay-Dale; Value_Code: 4k99; Power_W: 100mW; Value2: 0.1W; VDC_V: 75V; TempCo: 100 ppm/C; EIA_Code: E96; AEC Category: Q200; AEC Qualified: Y; AEC Grade: 0; SizeArea_mm2: 1.28; SizeX_mm: 1.6; SizeY_mm: 0.8; SizeZ_mm: 1
RP1-RP3 = CMP-0001777-2: Trimming Potentiometer, 50K, 0.5W, TH; Manufacturer: Bourns; CompType: Trimmer
SH-J1 SH-J2 = CMP-0003623-3: Shunt, 100mil, Gold plated, Black; Alternate PartNumber: 969102-0000-DA; Manufacturer: Samtec; Alternate Manufacturer: 3M; Value: 1x2
TP1 TP2 = CMP-0003825-1: 1mm Test Point, SMT; Manufacturer: Any
U1 = CMP-0091750-2: 100-V Brushed DC Gate Driver; Manufacturer: Texas Instruments; AEC Qualified: No; TaMax_C: +125°C; Standoff Height: 0mm; SizeZ_mm: 1mm; CompType: IC; Number Of Outputs: 2; Min Supply Voltage: 5V; AEC Category: Q200; TaMin_C: -40°C; TJmax_C: +150°C; Switching Frequency: 200kHz; Nominal Supply Current: 825uA; Max Supply Voltage: 20V
U2 = CMP-0066087-1: 7.5-100V Wide Vin, 600mA Constant On-Time Synchronous Buck Regulator, NGU0008B (WSON-8); Alternate PartNumber: LM5017SD/NOPB; Alternate Manufacturer: Texas Instruments; SizeAreaWB_mm2: 25.0; U/M: EA; SizeZ_mm: 0.8; SizeX_mm: 4.0; SizeArea_mm2: 16.0; CompType: IC
U3 = CMP-0080825-1: 500-mA, 25-V, Linear Voltage Regulators, DCY0004A (SOT-223-4); Alternate Manufacturer: Texas Instruments; Green_Lifecycle: Active; SizeAreaWB_mm2: 76.5; Green_REACh: Passed; SizeZ_mm: 1.8; SizeX_mm: 7; SizeY_mm: 6.5; SizeArea_mm2: 45.5; CompType: IC; AEC Qualified: N; AEC Category: Q200
U4 = CMP-0039637-1: 16 MHz Mixed Signal Microcontroller with 16 KB Flash, 512 B SRAM and 24 GPIOs, -40 to 85 degC, 20-pin SOP (PW), Green (RoHS & no Sb/Br); Manufacturer: Texas Instruments; Timers - 16-bit: 2; Brown Out Reset: Yes; SRAM(B): 512; Flash(KB): 16; ADC: 10-bit SAR; USCI_B (I2C & SPI): 1; ADC Channels: 8; GPIO: 24; SubFamily: Value Line
U5 = CMP-0013323-2: Bidirectional, Low- and High-Side Measurement, Multichannel, Voltage Output, Current-Sense Amplifiers, DGS0010A (VSSOP-10); Manufacturer: Texas Instruments; SizeX_mm: 4.9; SizeY_mm: 3; CompType: IC; SizeZ_mm: 1.1; SizeArea_mm2: 14.7; SizeAreaWB_mm2: 23.6; U/M: EA
U6 = CMP-0081556-1: Low-Power, Rail-to-Rail In and Out, 1-MHz Operational Amplifier, DCK0005A (SOT-SC70-5); Alternate PartNumber: TLV9001IDCKT; Alternate Manufacturer: Texas Instruments; SizeAreaWB_mm2: 9.3; SizeZ_mm: 1.1; SizeX_mm: 2.1; SizeY_mm: 2; SizeArea_mm2: 4.2; CompType: IC; AEC Qualified: N; AEC Category: Q200

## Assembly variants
001: not fitted C3 C17 C18 C19 C20 C21 C22 C23 C24 C25 C27 C28 C29 C30 C31 D4 D5 D6 D8 R1 R2 R15 R17 R19 R25 R31 R34 R39 R41 R45; alternate parts L1 -> CMP-0056117-1, R8 -> CMP-0026455-2, C9 -> CMP-0860984-1, C10 -> CMP-0007180-4, R5 -> CMP-0022620-4, R6 -> CMP-0021999-4, R9 -> CMP-0022874-5, R26 -> CMP-0015840-2, R33 -> CMP-0015840-2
